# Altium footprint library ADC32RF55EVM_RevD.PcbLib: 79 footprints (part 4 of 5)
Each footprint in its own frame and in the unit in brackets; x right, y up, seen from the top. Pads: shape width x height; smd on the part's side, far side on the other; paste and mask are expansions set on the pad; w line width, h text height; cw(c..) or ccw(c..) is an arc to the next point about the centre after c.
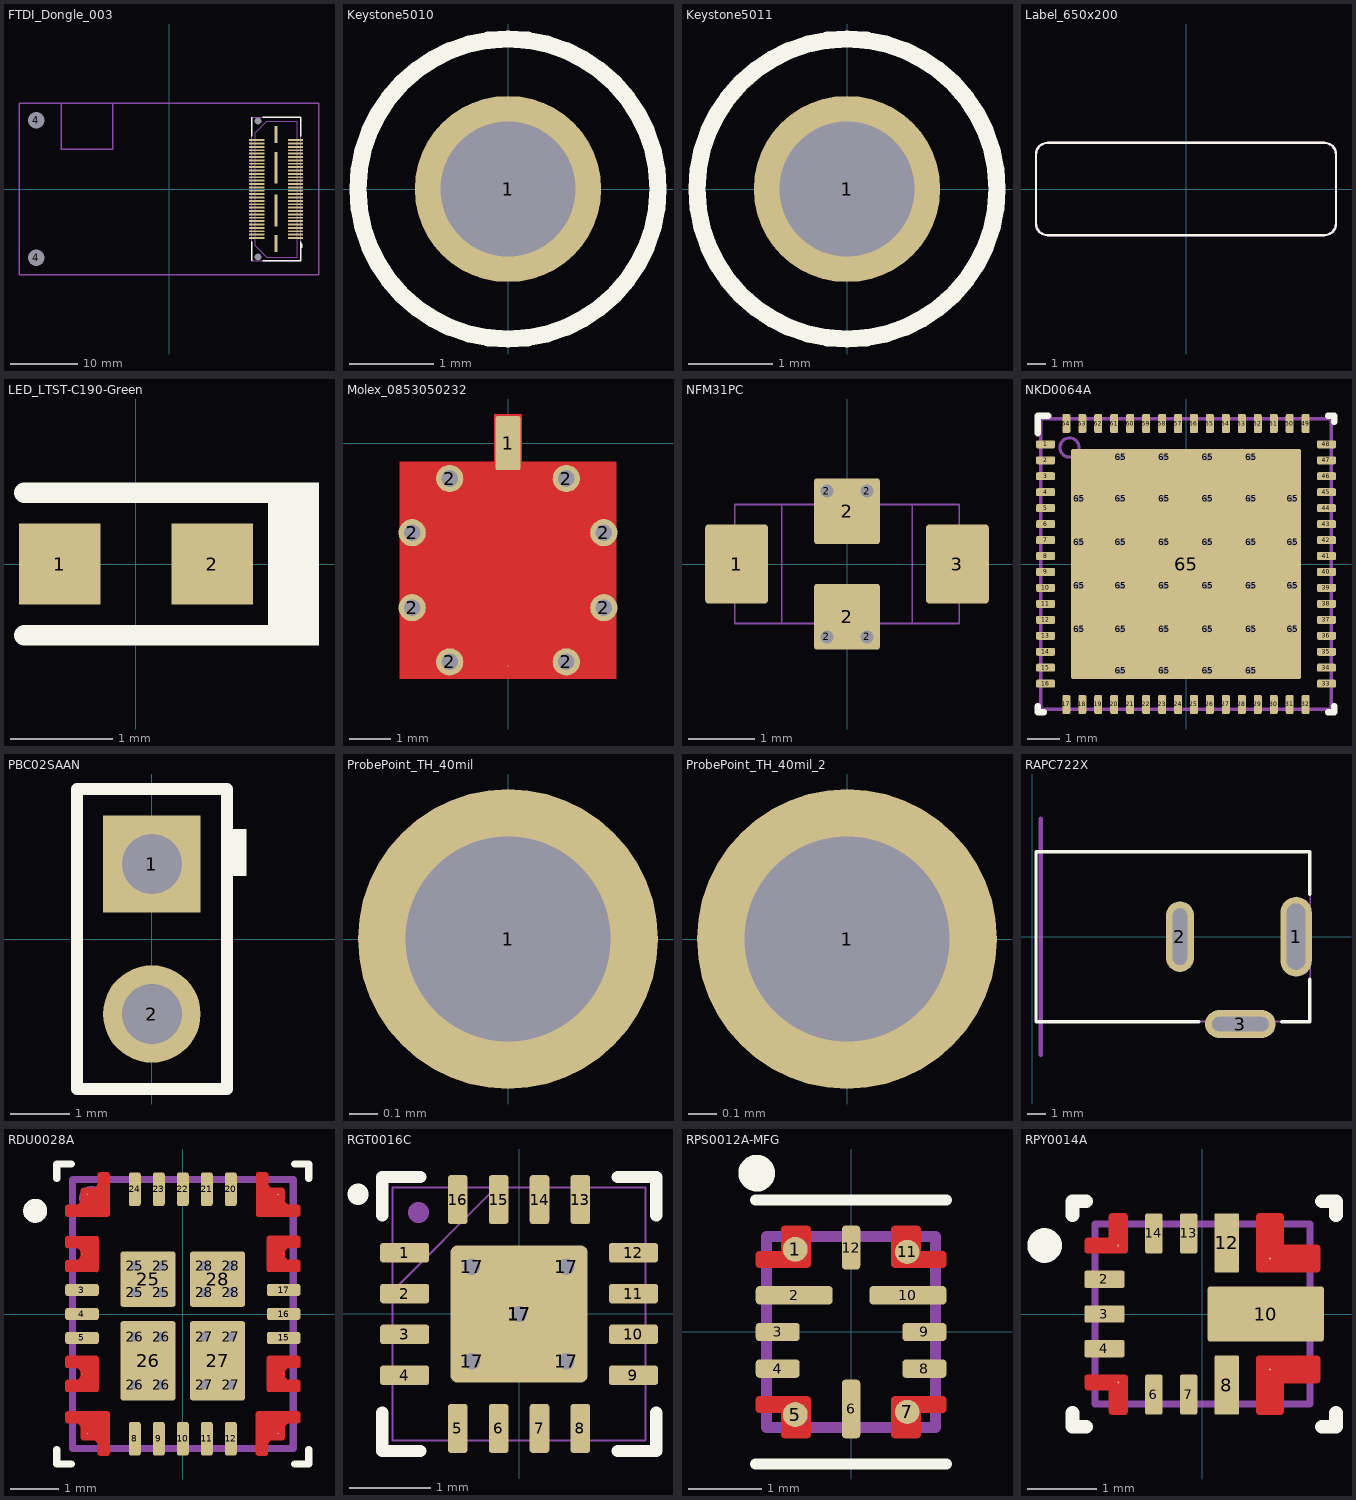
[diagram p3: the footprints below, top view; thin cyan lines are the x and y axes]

## FTDI_Dongle_003 [mm]
height 5.08
pads (68):
  rect 2.27x0.279 smd: 1(18.74,-7.25) 2(13.01,-7.25) 3(18.74,-6.75) 4(13.01,-6.75) 5(18.74,-6.25) 6(13.01,-6.25) 7(18.74,-5.75) 8(13.01,-5.75) 9(18.74,-5.25) 10(13.01,-5.25) 11(18.74,-4.75) 12(13.01,-4.75) 13(18.74,-4.25) 14(13.01,-4.25) 15(18.74,-3.75) 16(13.01,-3.75) 17(18.74,-3.25) 18(13.01,-3.25) 19(18.74,-2.75) 20(13.01,-2.75) 21(18.74,-2.25) 22(13.01,-2.25) 23(18.74,-1.75) 24(13.01,-1.75) 25(18.74,-1.25) 26(13.01,-1.25) 27(18.74,-0.75) 28(13.01,-0.75) 29(18.74,-0.25) 30(13.01,-0.25) 31(18.74,0.25) 32(13.01,0.25) 33(18.74,0.75) 34(13.01,0.75) 35(18.74,1.25) 36(13.01,1.25) 37(18.74,1.75) 38(13.01,1.75) 39(18.74,2.25) 40(13.01,2.25) 41(18.74,2.75) 42(13.01,2.75) 43(18.74,3.25) 44(13.01,3.25) 45(18.74,3.75) 46(13.01,3.75) 47(18.74,4.25) 48(13.01,4.25) 49(18.74,4.75) 50(13.01,4.75) 51(18.74,5.25) 52(13.01,5.25) 53(18.74,5.75) 54(13.01,5.75) 55(18.74,6.25) 56(13.01,6.25) 57(18.74,6.75) 58(13.01,6.75) 59(18.74,7.25) 60(13.01,7.25)
  round 2 hole 2.45 unplated: 4(-19.685,-10.16) 4(-19.685,10.16)
  round 0 hole 1.02 unplated: MH1(13.205,-10.065) MH2(13.205,10.065)
  rect 0.43x2.54 smd: MP1(15.875,-8.065) MP4(15.875,8.065)
  rect 0.43x4.7 smd: MP2(15.875,-3.175) MP3(15.875,3.175)
Top Overlay:
  region: 19.775,-8.1 19.495,-8.1 19.495,-8.7 19.775,-8.7
  lines w0.2: 12.255,-10.655 12.255,-7.79 ; 12.255,7.789 12.255,10.655 ; 13.875,-10.655 19.495,-10.655 19.495,-7.79 ; 13.875,10.655 19.495,10.655 19.495,7.789
Mechanical 5:
  drawing of 202 lines, arcs and shapes, not listed
  text ".Designator" at 12.764,-0.019 h0.64
  text "USB" at -12.798,9.102 h0.64
Mechanical 15:
  lines w0.203: -22.225,-12.7 -22.225,12.7 22.225,12.7 22.225,-12.7 -22.225,-12.7
3D body "Samtec-QSH-030-01-L-D-A.stp": height 3.25, standoff -0.75, extent 12.128,-10.674 19.621,10.636
3D body "FT4232 Donge RevA(003).x_t": height 10.54, standoff -0.08, extent -22.225,-12.7 22.225,13.2

## Keystone5010 [mil] "Keystone Multipurpose loops"
height 320
pads (1):
  round 87 hole 63: 1(0,0)
Top Overlay:
  circle w7.99: c0,0 r70
Mechanical 5:
  circle w5: c0,0 r69.46
  text ".Designator" at -55,-10 h30
3D body "Keystone_5010.stp": height 318.9, standoff -125.98, extent -63,-63 62.74,62.49

## Keystone5011 [mil] "Keystone Multipurpose loops"
height 320
pads (1):
  round 87 hole 63: 1(0,0)
Top Overlay:
  circle w7.99: c0,0 r70
Mechanical 5:
  circle w5: c0,0 r69.46
  text ".Designator" at -55,-10 h30
3D body "Keystone_5011.stp": height 318.9, standoff -125.98, extent -63,-63 62.74,62.49

## Label_650x200 [mil] "Thermal Transfer Label"
height 1
pads (1):
  round 1 on Mech13: 0(0,0)
Top Overlay:
  lines w5: -325,-75 ccw(c-300,-75) -300,-100 300,-100 ccw(c300,-75) 325,-75 325,75 ccw(c300,75) 300,100 -300,100 ccw(c-300,75) -325,75 -325,-75
Mechanical 5:
  lines w5: -325,-75 ccw(c-300,-75) -300,-100 300,-100 ccw(c300,-75) 325,-75 325,75 ccw(c300,75) 300,100 -300,100 ccw(c-300,75) -325,75 -325,-75
  text ".Designator" at -60,-20 h40
3D body: height 1, standoff 0, extent -325.02,-100.02 325.02,100.02

## LED_LTST-C190-Green [mm] "Lite-On"
height 0.9
pads (2):
  rect 0.8x0.8 smd: 1(-0.75,0) 2(0.75,0)
Top Overlay:
  region: 1.8,0.8 1.3,0.8 1.3,-0.8 1.8,-0.8
  lines w0.2: -1.1,-0.7 1.4,-0.7 ; -1.1,0.7 1.4,0.7
Mechanical 5:
  region: 1.8,0.75 1.3,0.75 1.3,-0.75 1.8,-0.75
  lines w0.1: -1.1,-0.7 1.4,-0.7 ; -1.1,0.7 1.4,0.7
  text ".Designator" at -0.254,0 h0.64
3D body: height 0.91, standoff 0.28, extent -0.6,-0.45 0.6,0.45
3D body "Lite-On_LTST_C190.stp": height 0.9, standoff 0, extent -0.85,-0.45 0.85,0.45

## Molex_0853050232 [mm] "Plug, 50 Ohm, Straight, SMT"
height 4.35
pads (10):
  rrect17% 0.6x1.3 smd: 1(0,0)
  round 0.654 hole 0.4 mask+0.05: 2(-2.3,-3.95) 2(-2.3,-2.15) 2(-1.4,-5.25) 2(-1.4,-0.85) 2(1.4,-5.25) 2(1.4,-0.85) 2(2.3,-3.95) 2(2.3,-2.15)
  round 0.025 smd: 2(0,-5.35)
Top Layer:
  pour cut-out: -0.33,0.699 -0.33,-0.698 0.33,-0.698 0.33,0.699
  pour cut-out: 0.998,-1.315 0.998,-0.45 -0.998,-0.45 -0.998,-1.321 -1.188,-1.431 -1.51,-1.728 -1.761,-2.087 -1.927,-2.492 -2.002,-2.924 -1.982,-3.361 -1.868,-3.784 -1.664,-4.172 -1.382,-4.507 -1.034,-4.773 -0.636,-4.957 -0.208,-5.051 0.23,-5.049 0.657,-4.953 1.054,-4.767 1.401,-4.499 1.681,-4.163 1.882,-3.773 1.994,-3.35 2.012,-2.912 1.934,-2.481 1.765,-2.077 1.512,-1.719 1.188,-1.424
  region: -2.6,-5.65 -2.6,-0.45 -1,-0.45 -1,-1.318 -1.183,-1.437 -1.504,-1.731 -1.753,-2.088 -1.92,-2.49 -1.996,-2.919 -1.977,-3.354 -1.864,-3.775 -1.663,-4.161 -1.383,-4.495 -1.038,-4.76 -0.643,-4.944 -0.218,-5.038 0.218,-5.038 0.643,-4.944 1.038,-4.76 1.383,-4.495 1.663,-4.161 1.864,-3.775 1.977,-3.354 1.996,-2.919 1.92,-2.49 1.753,-2.088 1.504,-1.731 1.183,-1.437 1,-1.318 1,-0.45 2.6,-0.45 2.6,-5.65
Mid-Layer 1:
  pour cut-out: -0.33,0.699 -0.33,-0.698 0.33,-0.698 0.33,0.699
  pour cut-out: 0.998,-1.315 0.998,-0.45 -0.998,-0.45 -0.998,-1.321 -1.188,-1.431 -1.51,-1.728 -1.761,-2.087 -1.927,-2.492 -2.002,-2.924 -1.982,-3.361 -1.868,-3.784 -1.664,-4.172 -1.382,-4.507 -1.034,-4.773 -0.636,-4.957 -0.208,-5.051 0.23,-5.049 0.657,-4.953 1.054,-4.767 1.401,-4.499 1.681,-4.163 1.882,-3.773 1.994,-3.35 2.012,-2.912 1.934,-2.481 1.765,-2.077 1.512,-1.719 1.188,-1.424
  pour cut-out: 0.998,-1.315 0.998,-0.45 -0.998,-0.45 -0.998,-1.321 -1.188,-1.431 -1.51,-1.728 -1.761,-2.087 -1.927,-2.492 -2.002,-2.924 -1.982,-3.361 -1.868,-3.784 -1.664,-4.172 -1.382,-4.507 -1.034,-4.773 -0.636,-4.957 -0.208,-5.051 0.23,-5.049 0.657,-4.953 1.054,-4.767 1.401,-4.499 1.681,-4.163 1.882,-3.773 1.994,-3.35 2.012,-2.912 1.934,-2.481 1.765,-2.077 1.512,-1.719 1.188,-1.424
  pour cut-out: 0.998,-1.315 0.998,-0.45 -0.998,-0.45 -0.998,-1.321 -1.188,-1.431 -1.51,-1.728 -1.761,-2.087 -1.927,-2.492 -2.002,-2.924 -1.982,-3.361 -1.868,-3.784 -1.664,-4.172 -1.382,-4.507 -1.034,-4.773 -0.636,-4.957 -0.208,-5.051 0.23,-5.049 0.657,-4.953 1.054,-4.767 1.401,-4.499 1.681,-4.163 1.882,-3.773 1.994,-3.35 2.012,-2.912 1.934,-2.481 1.765,-2.077 1.512,-1.719 1.188,-1.424
Mechanical 5:
  lines w0.1: -0.2,-0.55 -0.2,0.444 cw(c0,-3.025) 0.2,0.444 0.2,-0.55 ; -2.5,-4.311 ccw(c0,-3.05) -1.261,-5.55 ; -2.5,-4.311 -2.5,-1.789 ; -2.5,-4.311 -2.5,-5.127 ccw(c0,-3.05) -2.077,-5.55 -1.261,-5.55 ; -2.5,-1.789 cw(c0,-3.05) -1.261,-0.55 ; -2.5,-1.789 -2.5,-0.973 cw(c0,-3.05) -2.077,-0.55 -1.261,-0.55 ; -1.261,-5.55 1.261,-5.55 ; -1.261,-0.55 1.261,-0.55 ; 1.261,-5.55 ccw(c0,-3.05) 2.5,-4.311 ; 1.261,-5.55 2.077,-5.55 ccw(c0,-3.05) 2.5,-5.127 2.5,-4.311 ; 1.261,-0.55 cw(c0,-3.05) 2.5,-1.789 ; 1.261,-0.55 2.077,-0.55 cw(c0,-3.05) 2.5,-0.973 2.5,-1.789 ; 2.5,-4.311 2.5,-1.789
  text ".Designator" at -0.254,0 h0.64
3D body "0853050232.stp": height 4.1, standoff 0, extent -2.5,-5.55 2.5,0.45

## NFM31PC [mm]
height 4.27
pads (8):
  rrect10% 0.95x1.2 smd paste+0: 1(-1.675,0) 3(1.675,0)
  round 0.2 / inner round 0.454 / far side round 0.454 hole 0.2 mask+0.05: 2(-0.305,-1.105) 2(-0.305,1.105) 2(0.305,-1.105) 2(0.305,1.105)
  rrect10% 1x1 smd paste+0: 2(0,-0.8) 2(0,0.8)
Mechanical 5:
  lines w0.025: -1.702,-0.902 1.702,-0.902 ; -1.702,-0.902 -1.702,0.902 ; -1.702,-0.902 -1.702,0.902 ; -1.702,-0.902 -0.991,-0.902 ; -1.702,-0.902 -1.702,0.902 ; -1.702,-0.902 -0.991,-0.902 ; -1.702,-0.902 -1.702,0.902 ; -1.702,-0.902 1.702,-0.902 ; -1.702,0.902 -0.991,0.902 ; -1.702,0.902 1.702,0.902 ; -1.702,0.902 1.702,0.902 ; -1.702,0.902 -0.991,0.902 ; -0.991,-0.902 -0.991,0.902 ; -0.991,-0.902 -0.991,0.902 ; 0.991,-0.902 1.702,-0.902 ; 0.991,-0.902 0.991,0.902 ; 0.991,-0.902 0.991,0.902 ; 0.991,-0.902 1.702,-0.902 ; 0.991,0.902 1.702,0.902 ; 0.991,0.902 1.702,0.902 ; 1.702,-0.902 1.702,0.902 ; 1.702,-0.902 1.702,0.902 ; 1.702,-0.902 1.702,0.902 ; 1.702,-0.902 1.702,0.902
  text ".Designator" at -0.127,-0.212 h0.64
3D body "NFM31_MUR.step": height 1.5, standoff 0, extent -1.702,-0.902 1.702,0.902

## NKD0064A [mm] "QFN, 64-Leads, Body 9x9mm, Pitch 0.5mm"
height 0.8
pads (97):
  rrect40% 0.6x0.25 smd mask+0.07: 1(-4.4,3.75) 2(-4.4,3.25) 3(-4.4,2.75) 4(-4.4,2.25) 5(-4.4,1.75) 6(-4.4,1.25) 7(-4.4,0.75) 8(-4.4,0.25) 9(-4.4,-0.25) 10(-4.4,-0.75) 11(-4.4,-1.25) 12(-4.4,-1.75) 13(-4.4,-2.25) 14(-4.4,-2.75) 15(-4.4,-3.25) 16(-4.4,-3.75) 33(4.4,-3.75) 34(4.4,-3.25) 35(4.4,-2.75) 36(4.4,-2.25) 37(4.4,-1.75) 38(4.4,-1.25) 39(4.4,-0.75) 40(4.4,-0.25) 41(4.4,0.25) 42(4.4,0.75) 43(4.4,1.25) 44(4.4,1.75) 45(4.4,2.25) 46(4.4,2.75) 47(4.4,3.25) 48(4.4,3.75)
  rrect40% 0.25x0.6 smd mask+0.07: 17(-3.75,-4.4) 18(-3.25,-4.4) 19(-2.75,-4.4) 20(-2.25,-4.4) 21(-1.75,-4.4) 22(-1.25,-4.4) 23(-0.75,-4.4) 24(-0.25,-4.4) 25(0.25,-4.4) 26(0.75,-4.4) 27(1.25,-4.4) 28(1.75,-4.4) 29(2.25,-4.4) 30(2.75,-4.4) 31(3.25,-4.4) 32(3.75,-4.4) 49(3.75,4.4) 50(3.25,4.4) 51(2.75,4.4) 52(2.25,4.4) 53(1.75,4.4) 54(1.25,4.4) 55(0.75,4.4) 56(0.25,4.4) 57(-0.25,4.4) 58(-0.75,4.4) 59(-1.25,4.4) 60(-1.75,4.4) 61(-2.25,4.4) 62(-2.75,4.4) 63(-3.25,4.4) 64(-3.75,4.4)
  round 0.454 hole 0.2 mask+0.102: 65(-3.35,-2.04) 65(-3.35,-0.68) 65(-3.35,0.68) 65(-3.35,2.04) 65(-2.04,-3.35) 65(-2.04,-2.04) 65(-2.04,-0.68) 65(-2.04,0.68) 65(-2.04,2.04) 65(-2.04,3.35) 65(-0.68,-3.35) 65(-0.68,-2.04) 65(-0.68,-0.68) 65(-0.68,0.68) 65(-0.68,2.04) 65(-0.68,3.35) 65(0.68,-3.35) 65(0.68,-2.04) 65(0.68,-0.68) 65(0.68,0.68) 65(0.68,2.04) 65(0.68,3.35) 65(2.04,-3.35) 65(2.04,-2.04) 65(2.04,-0.68) 65(2.04,0.68) 65(2.04,2.04) 65(2.04,3.35) 65(3.35,-2.04) 65(3.35,-0.68) 65(3.35,0.68) 65(3.35,2.04)
  rrect1% 7.2x7.2 smd paste-3.6 mask+0.07: 65(0,0)
Top Overlay:
  lines w0.2: -4.65,-4.45 -4.65,-4.65 -4.45,-4.65 ; -4.65,4.1 -4.65,4.65 -4.32,4.65 ; 4.45,-4.65 4.65,-4.65 4.65,-4.45 ; 4.45,4.65 4.65,4.65 4.65,4.45
Top Paste:
  rectangle: -3.3,-3.3 -2.14,-2.14
  rectangle: -1.94,-3.3 -0.78,-2.14
  rectangle: -0.58,-3.3 0.58,-2.14
  rectangle: 0.78,-3.3 1.94,-2.14
  rectangle: 2.14,-3.3 3.3,-2.14
  rectangle: 2.14,-1.94 3.3,-0.78
  rectangle: 0.78,-1.94 1.94,-0.78
  rectangle: -0.58,-1.94 0.58,-0.78
  rectangle: -1.94,-1.94 -0.78,-0.78
  rectangle: -3.3,-1.94 -2.14,-0.78
  rectangle: -3.3,-0.58 -2.14,0.58
  rectangle: -1.94,-0.58 -0.78,0.58
  rectangle: -1.94,0.78 -0.78,1.94
  rectangle: -3.3,0.78 -2.14,1.94
  rectangle: -3.3,2.14 -2.14,3.3
  rectangle: -1.94,2.14 -0.78,3.3
  rectangle: -0.58,2.14 0.58,3.3
  rectangle: -0.58,0.78 0.58,1.94
  rectangle: 2.14,0.78 3.3,1.94
  rectangle: 2.14,2.14 3.3,3.3
  rectangle: 0.78,2.14 1.94,3.3
  rectangle: 0.78,0.78 1.94,1.94
  rectangle: 2.14,-0.58 3.3,0.58
  rectangle: 0.78,-0.58 1.94,0.58
  rectangle: -0.58,-0.58 0.58,0.58
Mechanical 5:
  circle w0.1: c-3.65,3.65 r0.3
  lines w0.1: -4.55,-4.55 4.55,-4.55 4.55,4.55 -4.55,4.55 -4.55,-4.55
  text ".Designator" at -0.254,0 h0.64
3D body: height 0.81, standoff 0.5, extent -3.949,3.351 -3.351,3.949
3D body: height 0.8, standoff 0, extent -4.549,-4.549 4.549,4.549

## PBC02SAAN [mm] "Sullins 100mil, 1x2, 230 mil above insulator"
height 8.382
pads (2):
  rect 1.65x1.65 hole 1.016: 1(0,1.27)
  round 1.65 hole 1.016: 2(0,-1.27)
Top Overlay:
  region: 1.3,1.864 1.3,1.064 1.6,1.064 1.6,1.864
  lines w0.2: -1.27,-2.54 1.27,-2.54 1.27,2.54 -1.27,2.54 -1.27,-2.54
Mechanical 5:
  lines w0.1: -1.27,-2.54 -1.27,2.54 1.27,2.54 1.27,-2.54 -1.27,-2.54
  text ".Designator" at -0.254,0 h0.64
3D body: height 8.38, standoff -3.05, extent -0.317,-1.587 0.317,-0.953
3D body: height 8.38, standoff -3.05, extent -0.317,0.953 0.317,1.587
3D body: height 2.54, standoff 0, extent -1.27,-2.54 1.27,2.54

## ProbePoint_TH_40mil [mil]
height 157
pads (1):
  round 41 hole 28: 1(0,0)
Top Overlay:
  text ".Text1" at 40,-17 h30
Bottom Overlay:
  text ".Text1" at -48,-18 h30
Mechanical 5:
  text ".Designator" at -20.5,0 h18

## ProbePoint_TH_40mil_2 [mil]
pads (1):
  round 41 hole 28: 1(0,0)
Top Overlay:
  text ".Text1" at 34,-11 h30
Bottom Overlay:
  text ".Text1" at -36.2,-15.93 h30
Mechanical 5:
  text ".Designator" at -20.5,0 h18

## RAPC722X [mm] "Conn_DC Jack"
height 11.176
pads (3):
  oval 1.7x4.3 hole 1.01 slot 3.56 at 90 deg: 1(14.194,0)
  oval 1.5x3.8 hole 0.76 slot 3.05 at 90 deg: 2(7.946,0)
  oval 3.8x1.5 hole 0.76 slot 3.05 at 0 deg: 3(11.197,-4.7)
Top Overlay:
  lines w0.178: 8.962,-4.572 0.199,-4.572 0.199,4.572 14.931,4.572 14.931,2.286 ; 13.407,-4.572 14.931,-4.572 14.931,-2.286
Mechanical 1:
  lines w0.254: 0.453,-6.35 0.453,6.35
  text "BOARD EDGE" at -0.254,-4.064 h0.89
Mechanical 5:
  lines w0.102: 0.226,-4.572 14.958,-4.572 14.958,4.572 0.226,4.572 0.226,-4.572
  lines w0.127: 9.946,-4.5 9.946,-4.9 12.446,-4.9 12.446,-4.5 ; 13.996,-1.5 14.396,-1.5 ; 13.996,1.5 14.396,1.5 ; 14.896,-1.5 14.396,-1.5 ; 14.896,1.5 14.396,1.5 ; 14.396,-1.5 14.396,1.5
  text ".Designator" at -0.254,0 h0.64
3D body "RAPC722X--3DModel-STEP-269445.STEP": height 10.92, standoff -3.56, extent 0.584,-4.966 15.062,4.559

## RDU0028A [mm]
height 4.27
pads (44):
  round 0.025 smd mask+0.05: 1(-1.987,2.487) 2(-2.1,1.25) 6(-2.1,-1.25) 7(-1.987,-2.488) 13(1.987,-2.488) 14(2.1,-1.25) 18(2.1,1.25) 19(1.988,2.488)
  rrect40% 0.7x0.25 smd paste+0 mask+0.05: 3(-2.1,0.5) 4(-2.1,0) 5(-2.1,-0.5) 15(2.1,-0.5) 16(2.1,0) 17(2.1,0.5)
  rrect40% 0.25x0.7 smd paste+0 mask+0.05: 8(-1,-2.6) 9(-0.5,-2.6) 10(0,-2.6) 11(0.5,-2.6) 12(1,-2.6) 20(1,2.6) 21(0.5,2.6) 22(0,2.6) 23(-0.5,2.6) 24(-1,2.6)
  round 0.454 hole 0.2 mask+0.102: 25(-1,1) 25(-1,0.45) 25(-0.45,1) 25(-0.45,0.45) 26(-1,-1.475) 26(-1,-0.475) 26(-0.45,-1.475) 26(-0.45,-0.475) 27(0.45,-1.475) 27(0.45,-0.475) 27(1,-1.475) 27(1,-0.475) 28(0.45,1) 28(0.45,0.45) 28(1,1) 28(1,0.45)
  rrect9% 1.15x1.15 smd paste-1000 mask+0.05: 25(-0.725,0.725) 28(0.725,0.725)
  rrect9% 1.15x1.65 smd paste-1000 mask+0.05: 26(-0.725,-0.975) 27(0.725,-0.975)
Top Layer:
  region: 1.575,2.95 1.565,2.95 1.547,2.942 1.533,2.928 1.525,2.91 1.525,2.9 1.525,2.075 1.525,2.065 1.533,2.047 1.547,2.033 1.565,2.025 1.575,2.025 2.4,2.025 2.409,2.026 2.426,2.034 2.438,2.048 2.445,2.066 2.445,2.075 2.45,2.225 2.45,2.235 2.442,2.253 2.428,2.267 2.41,2.275 2.4,2.275 2.225,2.275 2.206,2.277 2.169,2.292 2.142,2.319 2.127,2.356 2.125,2.375 2.125,2.575 2.125,2.585 2.117,2.603 2.103,2.617 2.085,2.625 2.075,2.625 1.875,2.625 1.856,2.627 1.819,2.642 1.792,2.669 1.777,2.706 1.775,2.725 1.775,2.9 1.775,2.91 1.767,2.928 1.753,2.942 1.735,2.95 1.725,2.95
  region: 2.4,-1.625 1.8,-1.625 1.79,-1.625 1.772,-1.617 1.758,-1.603 1.75,-1.585 1.75,-1.575 1.75,-0.925 1.75,-0.915 1.758,-0.897 1.772,-0.883 1.79,-0.875 1.8,-0.875 2.4,-0.875 2.41,-0.875 2.428,-0.883 2.442,-0.897 2.45,-0.915 2.45,-0.925 2.45,-1.075 2.45,-1.085 2.442,-1.103 2.428,-1.117 2.41,-1.125 2.4,-1.125 2.225,-1.125 2.206,-1.127 2.169,-1.142 2.142,-1.169 2.127,-1.205 2.125,-1.225 2.125,-1.275 2.127,-1.294 2.142,-1.331 2.169,-1.358 2.206,-1.373 2.225,-1.375 2.4,-1.375 2.41,-1.375 2.428,-1.383 2.442,-1.397 2.45,-1.415 2.45,-1.425 2.45,-1.575 2.45,-1.585 2.442,-1.603 2.428,-1.617 2.41,-1.625
  region: 1.575,-2.95 1.565,-2.95 1.547,-2.942 1.533,-2.928 1.525,-2.91 1.525,-2.9 1.525,-2.075 1.525,-2.065 1.533,-2.047 1.547,-2.033 1.565,-2.025 1.575,-2.025 2.4,-2.025 2.409,-2.026 2.426,-2.034 2.438,-2.048 2.445,-2.066 2.445,-2.075 2.45,-2.225 2.45,-2.235 2.442,-2.253 2.428,-2.267 2.41,-2.275 2.4,-2.275 2.225,-2.275 2.205,-2.277 2.169,-2.292 2.142,-2.319 2.127,-2.356 2.125,-2.375 2.125,-2.575 2.125,-2.585 2.117,-2.603 2.103,-2.617 2.085,-2.625 2.075,-2.625 1.875,-2.625 1.855,-2.627 1.819,-2.642 1.792,-2.669 1.777,-2.706 1.775,-2.725 1.775,-2.9 1.775,-2.91 1.767,-2.928 1.753,-2.942 1.735,-2.95 1.725,-2.95
  region: -1.575,2.95 -1.565,2.95 -1.547,2.942 -1.533,2.928 -1.525,2.91 -1.525,2.9 -1.525,2.075 -1.525,2.065 -1.533,2.047 -1.547,2.033 -1.565,2.025 -1.575,2.025 -2.4,2.025 -2.409,2.026 -2.426,2.034 -2.438,2.048 -2.445,2.066 -2.445,2.075 -2.45,2.225 -2.45,2.235 -2.442,2.253 -2.428,2.267 -2.41,2.275 -2.4,2.275 -2.225,2.275 -2.205,2.277 -2.169,2.292 -2.142,2.319 -2.127,2.355 -2.125,2.375 -2.125,2.575 -2.125,2.585 -2.117,2.603 -2.103,2.617 -2.085,2.625 -2.075,2.625 -1.875,2.625 -1.855,2.627 -1.819,2.642 -1.792,2.669 -1.777,2.705 -1.775,2.725 -1.775,2.9 -1.775,2.91 -1.767,2.928 -1.753,2.942 -1.735,2.95 -1.725,2.95
  region: -1.575,-2.95 -1.565,-2.95 -1.547,-2.942 -1.533,-2.928 -1.525,-2.91 -1.525,-2.9 -1.525,-2.075 -1.525,-2.065 -1.533,-2.047 -1.547,-2.033 -1.565,-2.025 -1.575,-2.025 -2.4,-2.025 -2.409,-2.026 -2.426,-2.034 -2.438,-2.048 -2.445,-2.066 -2.445,-2.075 -2.45,-2.225 -2.45,-2.235 -2.442,-2.253 -2.428,-2.267 -2.41,-2.275 -2.4,-2.275 -2.225,-2.275 -2.205,-2.277 -2.169,-2.292 -2.142,-2.319 -2.127,-2.356 -2.125,-2.375 -2.125,-2.575 -2.125,-2.585 -2.117,-2.603 -2.103,-2.617 -2.085,-2.625 -2.075,-2.625 -1.875,-2.625 -1.855,-2.627 -1.819,-2.642 -1.792,-2.669 -1.777,-2.706 -1.775,-2.725 -1.775,-2.9 -1.775,-2.91 -1.767,-2.928 -1.753,-2.942 -1.735,-2.95 -1.725,-2.95
  region: -2.4,-0.875 -1.8,-0.875 -1.79,-0.875 -1.772,-0.883 -1.758,-0.897 -1.75,-0.915 -1.75,-0.925 -1.75,-1.575 -1.75,-1.585 -1.758,-1.603 -1.772,-1.617 -1.79,-1.625 -1.8,-1.625 -2.4,-1.625 -2.41,-1.625 -2.428,-1.617 -2.442,-1.603 -2.45,-1.585 -2.45,-1.575 -2.45,-1.425 -2.45,-1.415 -2.442,-1.397 -2.428,-1.383 -2.41,-1.375 -2.4,-1.375 -2.225,-1.375 -2.205,-1.373 -2.169,-1.358 -2.142,-1.331 -2.127,-1.294 -2.125,-1.275 -2.125,-1.225 -2.127,-1.205 -2.142,-1.169 -2.169,-1.142 -2.205,-1.127 -2.225,-1.125 -2.4,-1.125 -2.41,-1.125 -2.428,-1.117 -2.442,-1.103 -2.45,-1.085 -2.45,-1.075 -2.45,-0.925 -2.45,-0.915 -2.442,-0.897 -2.428,-0.883 -2.41,-0.875
  region: -2.4,1.625 -1.8,1.625 -1.79,1.625 -1.772,1.617 -1.758,1.603 -1.75,1.585 -1.75,1.575 -1.75,0.925 -1.75,0.915 -1.758,0.897 -1.772,0.883 -1.79,0.875 -1.8,0.875 -2.4,0.875 -2.41,0.875 -2.428,0.883 -2.442,0.897 -2.45,0.915 -2.45,0.925 -2.45,1.075 -2.45,1.085 -2.442,1.103 -2.428,1.117 -2.41,1.125 -2.4,1.125 -2.225,1.125 -2.205,1.127 -2.169,1.142 -2.142,1.169 -2.127,1.205 -2.125,1.225 -2.125,1.275 -2.127,1.295 -2.142,1.331 -2.169,1.358 -2.205,1.373 -2.225,1.375 -2.4,1.375 -2.41,1.375 -2.428,1.383 -2.442,1.397 -2.45,1.415 -2.45,1.425 -2.45,1.575 -2.45,1.585 -2.442,1.603 -2.428,1.617 -2.41,1.625
  region: 2.4,0.875 1.8,0.875 1.79,0.875 1.772,0.883 1.758,0.897 1.75,0.915 1.75,0.925 1.75,1.575 1.75,1.585 1.758,1.603 1.772,1.617 1.79,1.625 1.8,1.625 2.4,1.625 2.41,1.625 2.428,1.617 2.442,1.603 2.45,1.585 2.45,1.575 2.45,1.425 2.45,1.415 2.442,1.397 2.428,1.383 2.41,1.375 2.4,1.375 2.225,1.375 2.206,1.373 2.169,1.358 2.142,1.331 2.127,1.295 2.125,1.275 2.125,1.225 2.127,1.206 2.142,1.169 2.169,1.142 2.206,1.127 2.225,1.125 2.4,1.125 2.41,1.125 2.428,1.117 2.442,1.103 2.45,1.085 2.45,1.075 2.45,0.925 2.45,0.915 2.442,0.897 2.428,0.883 2.41,0.875
Top Overlay:
  circle w0.25: c-3.075,2.15 r0.125
  lines w0.15: -2.625,-2.825 -2.625,-3.125 -2.325,-3.125 ; -2.625,2.825 -2.625,3.125 -2.325,3.125 ; 2.325,-3.125 2.625,-3.125 2.625,-2.825 ; 2.325,3.125 2.625,3.125 2.625,2.825
Top Paste:
  region: -1.265,-1.68 -1.265,-0.27 -1.265,-0.26 -1.257,-0.242 -1.243,-0.228 -1.225,-0.22 -1.215,-0.22 -0.235,-0.22 -0.225,-0.22 -0.207,-0.228 -0.193,-0.242 -0.185,-0.26 -0.185,-0.27 -0.185,-1.68 -0.185,-1.69 -0.193,-1.708 -0.207,-1.722 -0.225,-1.73 -0.235,-1.73 -1.215,-1.73 -1.225,-1.73 -1.243,-1.722 -1.257,-1.708 -1.265,-1.69
  region: 1.215,-0.22 1.225,-0.22 1.243,-0.228 1.257,-0.242 1.265,-0.26 1.265,-0.27 1.265,-1.68 1.265,-1.69 1.257,-1.708 1.243,-1.722 1.225,-1.73 1.215,-1.73 0.235,-1.73 0.225,-1.73 0.207,-1.722 0.193,-1.708 0.185,-1.69 0.185,-1.68 0.185,-0.27 0.185,-0.26 0.193,-0.242 0.207,-0.228 0.225,-0.22 0.235,-0.22
  region: 1.265,0.235 1.265,0.225 1.257,0.207 1.243,0.193 1.225,0.185 1.215,0.185 0.235,0.185 0.225,0.185 0.207,0.193 0.193,0.207 0.185,0.225 0.185,0.235 0.185,1.215 0.185,1.225 0.193,1.243 0.207,1.257 0.225,1.265 0.235,1.265 1.215,1.265 1.225,1.265 1.243,1.257 1.257,1.243 1.265,1.225 1.265,1.215
  region: -1.215,0.185 -1.225,0.185 -1.243,0.193 -1.257,0.207 -1.265,0.225 -1.265,0.235 -1.265,1.215 -1.265,1.225 -1.257,1.243 -1.243,1.257 -1.225,1.265 -1.215,1.265 -0.235,1.265 -0.225,1.265 -0.207,1.257 -0.193,1.243 -0.185,1.225 -0.185,1.215 -0.185,0.235 -0.185,0.225 -0.193,0.207 -0.207,0.193 -0.225,0.185 -0.235,0.185
Mechanical 5:
  circle w0.254: c-1.905,2.413 r0.127
  lines w0.15: -2.3,-2.8 -2.3,2.8 2.3,2.8 2.3,-2.8 -2.3,-2.8
  text ".Designator" at -0.127,0.339 h0.64
3D body "IC_TPSM82912RDUR_B0QFN28.STEP": height 0.25, standoff 0, extent -2.55,-3.05 2.55,3.05

## RGT0016C [mm]
pads (22):
  rrect30% 0.6x0.24 smd paste+0 mask+0.07: 1(-1.4,0.75) 2(-1.4,0.25) 3(-1.4,-0.25) 4(-1.4,-0.75) 9(1.4,-0.75) 10(1.4,-0.25) 11(1.4,0.25) 12(1.4,0.75)
  rrect30% 0.24x0.6 smd paste+0 mask+0.07: 5(-0.75,-1.4) 6(-0.25,-1.4) 7(0.25,-1.4) 8(0.75,-1.4) 13(0.75,1.4) 14(0.25,1.4) 15(-0.25,1.4) 16(-0.75,1.4)
  round 0.454 hole 0.2 mask+0.05: 17(-0.58,-0.58) 17(-0.58,0.58) 17(0,0) 17(0.58,-0.58) 17(0.58,0.58)
  rrect10% 1.68x1.68 smd paste-0.065 mask+0.07: 17(0,0)
Top Overlay:
  circle w0.254: c-1.969,1.465 r0.002
  lines w0.152: -1.676,-1.21 -1.676,-1.676 -1.21,-1.676 ; -1.676,1.21 -1.676,1.676 -1.21,1.676 ; 1.21,-1.676 1.676,-1.676 1.676,-1.21 ; 1.21,1.676 1.676,1.676 1.676,1.21
Mechanical 5:
  circle w0.254: c-1.233,1.242 r0.002
  lines w0.025: -1.549,0.279 -0.279,1.549 ; -1.549,-1.549 1.549,-1.549 1.549,1.549 -1.549,1.549 -1.549,-1.549 ; -1.549,-0.903 -1.549,-0.598 -1.549,-0.903 ; -1.549,-0.402 -1.549,-0.098 -1.549,-0.402 ; -1.549,0.098 -1.549,0.402 -1.549,0.098 ; -1.549,0.598 -1.549,0.903 -1.549,0.598 ; -0.903,-1.549 -0.598,-1.549 -0.903,-1.549 ; -0.903,1.549 -0.598,1.549 -0.903,1.549 ; -0.402,-1.549 -0.098,-1.549 -0.402,-1.549 ; -0.402,1.549 -0.098,1.549 -0.402,1.549 ; 0.098,-1.549 0.402,-1.549 0.098,-1.549 ; 0.098,1.549 0.402,1.549 0.098,1.549 ; 0.598,-1.549 0.903,-1.549 0.598,-1.549 ; 0.598,1.549 0.903,1.549 0.598,1.549 ; 1.549,-0.903 1.549,-0.598 1.549,-0.903 ; 1.549,-0.402 1.549,-0.098 1.549,-0.402 ; 1.549,0.098 1.549,0.402 1.549,0.098 ; 1.549,0.598 1.549,0.903 1.549,0.598
3D body "RGT0016C.step": height 1, standoff -0.03, extent -1.502,-1.502 1.502,1.502

## RPS0012A-MFG [mm]
height 4.27
pads (12):
  round 0.34 smd paste+0 mask+0: 1(-0.761,1.127) 5(-0.761,-1.127)
  rrect40% 1.05x0.25 smd paste+0 mask+0: 2(-0.775,0.5) 10(0.775,0.5)
  rrect40% 0.6x0.25 smd paste+0 mask+0: 3(-1,0) 4(-1,-0.5) 8(1,-0.5) 9(1,0)
  rrect40% 0.25x0.8 smd paste+0 mask+0: 6(0,-1.05)
  round 0.332 smd paste+0 mask+0: 7(0.766,-1.091) 11(0.766,1.091)
  rrect40% 0.25x0.6 smd paste+0 mask+0: 12(0,1.15)
Top Layer:
  region: 1.25,-1.1 0.95,-1.1 0.95,-1.4 0.95,-1.41 0.942,-1.428 0.928,-1.442 0.91,-1.45 0.9,-1.45 0.6,-1.45 0.59,-1.45 0.572,-1.442 0.558,-1.428 0.55,-1.41 0.55,-1.4 0.55,-0.925 0.55,-0.915 0.558,-0.897 0.572,-0.883 0.59,-0.875 0.6,-0.875 1.25,-0.875 1.26,-0.875 1.278,-0.883 1.292,-0.897 1.3,-0.915 1.3,-0.925 1.3,-1.05 1.3,-1.06 1.292,-1.078 1.278,-1.092 1.26,-1.1
  region: -1.25,-1.1 -0.95,-1.1 -0.95,-1.4 -0.95,-1.41 -0.942,-1.428 -0.928,-1.442 -0.91,-1.45 -0.9,-1.45 -0.6,-1.45 -0.59,-1.45 -0.572,-1.442 -0.558,-1.428 -0.55,-1.41 -0.55,-1.4 -0.55,-0.925 -0.55,-0.915 -0.558,-0.897 -0.572,-0.883 -0.59,-0.875 -0.6,-0.875 -1.25,-0.875 -1.26,-0.875 -1.278,-0.883 -1.292,-0.897 -1.3,-0.915 -1.3,-0.925 -1.3,-1.05 -1.3,-1.06 -1.292,-1.078 -1.278,-1.092 -1.26,-1.1
  region: -1.25,1.1 -0.95,1.1 -0.95,1.4 -0.95,1.41 -0.942,1.428 -0.928,1.442 -0.91,1.45 -0.9,1.45 -0.6,1.45 -0.59,1.45 -0.572,1.442 -0.558,1.428 -0.55,1.41 -0.55,1.4 -0.55,0.925 -0.55,0.915 -0.558,0.897 -0.572,0.883 -0.59,0.875 -0.6,0.875 -1.25,0.875 -1.26,0.875 -1.278,0.883 -1.292,0.897 -1.3,0.915 -1.3,0.925 -1.3,1.05 -1.3,1.06 -1.292,1.078 -1.278,1.092 -1.26,1.1
  region: 1.25,1.1 0.95,1.1 0.95,1.4 0.95,1.41 0.942,1.428 0.928,1.442 0.91,1.45 0.9,1.45 0.6,1.45 0.59,1.45 0.572,1.442 0.558,1.428 0.55,1.41 0.55,1.4 0.55,0.925 0.55,0.915 0.558,0.897 0.572,0.883 0.59,0.875 0.6,0.875 1.25,0.875 1.26,0.875 1.278,0.883 1.292,0.897 1.3,0.915 1.3,0.925 1.3,1.05 1.3,1.06 1.292,1.078 1.278,1.092 1.26,1.1
Top Overlay:
  circle w0.25: c-1.286,2.165 r0.125
  lines w0.15: -1.3,-1.8 1.3,-1.8 ; -1.3,1.8 1.3,1.8
Mechanical 5:
  lines w0.15: -1.15,-1.3 1.15,-1.3 1.15,1.3 -1.15,1.3 -1.15,-1.3
  text ".Designator" at 0.05,0.217 h0.5
3D body "IC_TPS7A5301RPSR_VQFN-HR-12.STEP": height 1, standoff 0, extent -1.1,-1.25 1.1,1.25

## RPY0014A [mm]
height 4.27
pads (14):
  round 0.025 smd mask+0.05: 1(-1.213,0.987) 5(-1.212,-0.988) 9(0.975,-0.8) 11(0.975,0.8)
  rrect20% 0.575x0.25 smd paste+0 mask+0.05: 2(-1.412,0.5) 3(-1.412,0) 4(-1.412,-0.5)
  rrect20% 0.25x0.575 smd paste+0 mask+0.05: 6(-0.7,-1.162) 7(-0.2,-1.162) 13(-0.2,1.162) 14(-0.7,1.162)
  rrect10% 0.35x0.851 smd paste+0 mask+0.05: 8(0.35,-1.025) 12(0.35,1.025)
  rrect10% 1.675x0.8 smd paste-0.825 mask-0.826: 10(0.913,0)
Top Layer:
  region: -1.115,-0.875 -1.107,-0.875 -1.092,-0.881 -1.081,-0.892 -1.075,-0.907 -1.075,-0.915 -1.075,-1.4 -1.075,-1.405 -1.075,-1.414 -1.082,-1.431 -1.094,-1.443 -1.111,-1.45 -1.12,-1.45 -1.3,-1.45 -1.31,-1.45 -1.328,-1.443 -1.342,-1.428 -1.35,-1.41 -1.35,-1.4 -1.35,-1.1 -1.655,-1.1 -1.664,-1.1 -1.68,-1.093 -1.693,-1.081 -1.7,-1.064 -1.7,-1.055 -1.7,-0.915 -1.7,-0.907 -1.694,-0.892 -1.683,-0.881 -1.668,-0.875 -1.66,-0.875
  region: -1.115,0.875 -1.107,0.875 -1.092,0.881 -1.081,0.892 -1.075,0.907 -1.075,0.915 -1.075,1.4 -1.075,1.405 -1.075,1.414 -1.082,1.43 -1.095,1.443 -1.111,1.45 -1.12,1.45 -1.3,1.45 -1.31,1.45 -1.328,1.442 -1.342,1.428 -1.35,1.41 -1.35,1.4 -1.35,1.1 -1.655,1.1 -1.664,1.1 -1.68,1.093 -1.693,1.08 -1.7,1.064 -1.7,1.055 -1.7,0.915 -1.7,0.907 -1.694,0.892 -1.683,0.881 -1.668,0.875 -1.66,0.875
  region: 1.237,-0.6 1.65,-0.6 1.66,-0.6 1.678,-0.608 1.692,-0.622 1.7,-0.64 1.7,-0.65 1.7,-0.95 1.7,-0.96 1.692,-0.978 1.678,-0.992 1.66,-1 1.65,-1 1.175,-1 1.175,-1.4 1.175,-1.41 1.167,-1.428 1.153,-1.442 1.135,-1.45 1.125,-1.45 0.82,-1.45 0.811,-1.45 0.795,-1.443 0.782,-1.43 0.775,-1.414 0.775,-1.405 0.775,-0.64 0.775,-0.632 0.781,-0.617 0.792,-0.606 0.807,-0.6 0.815,-0.6 0.874,-0.6
  region: 1.237,0.6 1.65,0.6 1.66,0.6 1.678,0.608 1.692,0.622 1.7,0.64 1.7,0.65 1.7,0.95 1.7,0.96 1.692,0.978 1.678,0.992 1.66,1 1.65,1 1.175,1 1.175,1.4 1.175,1.41 1.167,1.428 1.153,1.442 1.135,1.45 1.125,1.45 0.82,1.45 0.811,1.45 0.795,1.443 0.782,1.43 0.775,1.414 0.775,1.405 0.775,0.64 0.775,0.632 0.781,0.617 0.792,0.606 0.807,0.6 0.815,0.6 0.874,0.6
Top Overlay:
  circle w0.25: c-2.275,0.988 r0.125
  lines w0.2: -1.875,-1.425 -1.875,-1.625 -1.675,-1.625 ; -1.875,1.425 -1.875,1.625 -1.675,1.625 ; 1.725,-1.625 1.925,-1.625 1.925,-1.425 ; 1.725,1.625 1.925,1.625 1.925,1.425
Top Paste:
  drawing of 5 lines, arcs and shapes, not listed
Top Solder:
  region: 0.125,-0.3 0.125,-0.31 0.133,-0.328 0.147,-0.342 0.165,-0.35 0.175,-0.35 1.65,-0.35 1.66,-0.35 1.678,-0.342 1.692,-0.328 1.7,-0.31 1.7,-0.3 1.7,-0.175 1.7,-0.165 1.692,-0.147 1.678,-0.133 1.66,-0.125 1.65,-0.125 1.35,-0.125 1.35,0.125 1.65,0.125 1.66,0.125 1.678,0.133 1.692,0.147 1.7,0.165 1.7,0.175 1.7,0.3 1.7,0.31 1.692,0.328 1.678,0.342 1.66,0.35 1.65,0.35 0.175,0.35 0.165,0.35 0.147,0.342 0.133,0.328 0.125,0.31 0.125,0.3
Mechanical 5:
  lines w0.1: -1.55,-1.3 1.55,-1.3 1.55,1.3 -1.55,1.3 -1.55,-1.3
  text ".Designator" at -0.254,0 h0.64
3D body: height 1.01, standoff 0, extent -1.312,0.888 -1.112,1.088
3D body "RPY0014A.stp": height 1, standoff 0, extent -1.5,-1.25 1.5,1.25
